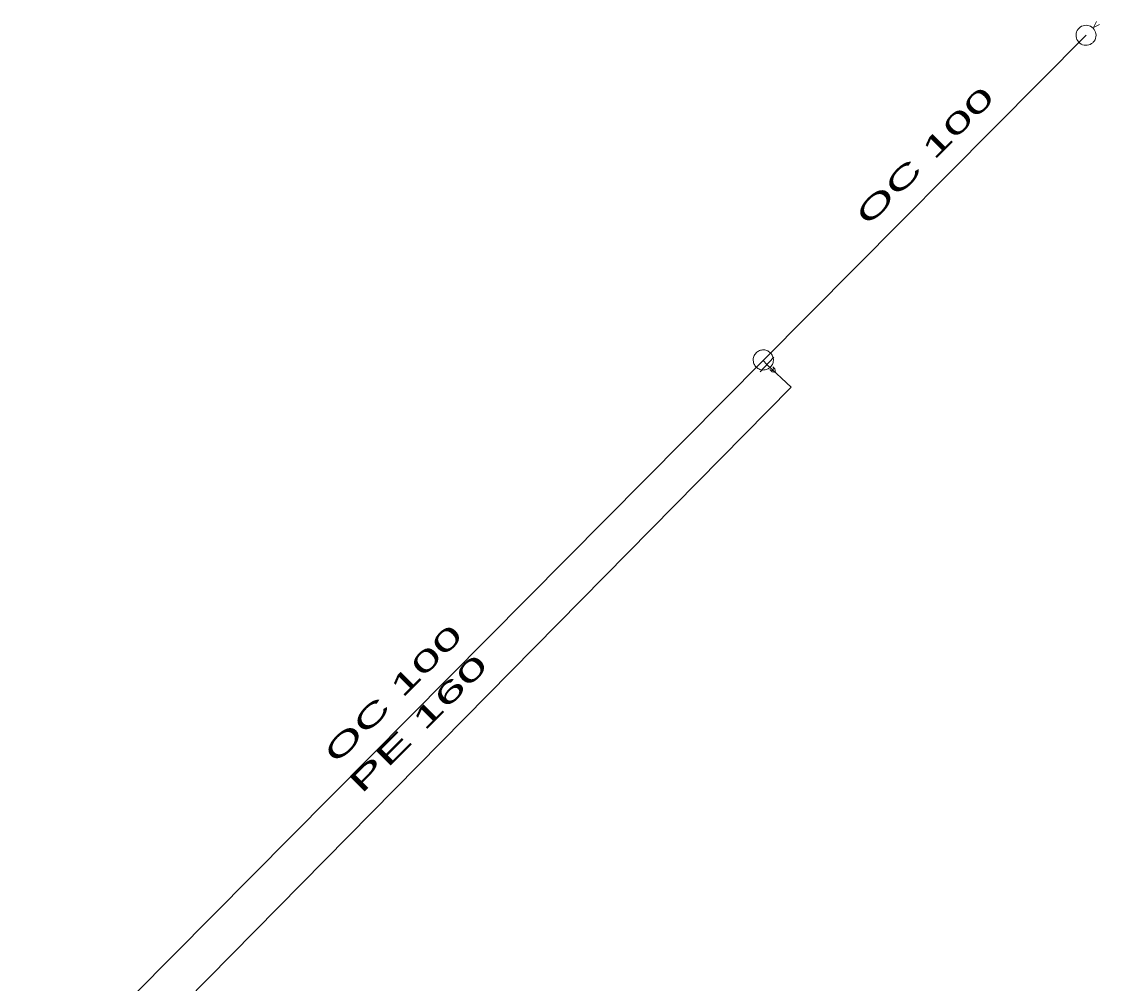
# Model space of a CAD drawing. Extents: x -807203 to -805207, y -993656 to -992505.
# Drawn here: x -806398.8 to -806345.3, y -992839.2 to -992791.5 of the extents above; entities that cross this region are included whole.
import ezdxf

# ---------------------------------------------------------------- set-up
doc = ezdxf.new("R2010")
doc.units = 0
doc.header["$LTSCALE"] = 0.4
for name, color, linetype, lineweight in [('1', 7, 'Continuous', 13), ('14', 7, 'Continuous', 25), ('17', 7, 'Continuous', 25), ('23', 7, 'Continuous', 13), ('34', 7, 'Continuous', 13)]:
    doc.layers.add(name, color=color, linetype=linetype, lineweight=lineweight)

msp = doc.modelspace()

# ---------------------------------------------------------------- linework, layer by layer
at = {"layer": '14', "lineweight": 13}
msp.add_line((-806361.818, -992808.52), (-806361.995, -992808.32), dxfattribs=at)
at = {"layer": '17'}
msp.add_line((-806345.978, -992792.175), (-806361.995, -992808.32), dxfattribs=at)
for points in [[(-806361.995, -992808.32), (-806393.217, -992839.791), (-806398.804, -992845.506)], [(-806397.651, -992847.204), (-806360.609, -992809.633), (-806361.818, -992808.52)]]:
    msp.add_lwpolyline(points, dxfattribs=at)
at = {"layer": '23'}
msp.add_line((-806361.595, -992808.837), (-806361.457, -992808.697), dxfattribs=at)
msp.add_lwpolyline([(-806345.619, -992792.52), (-806345.57, -992792.46), (-806345.531, -992792.394), (-806345.502, -992792.322), (-806345.485, -992792.246), (-806345.48, -992792.169), (-806345.487, -992792.092), (-806345.505, -992792.018), (-806345.535, -992791.947), (-806345.576, -992791.881), (-806345.626, -992791.822), (-806345.685, -992791.772), (-806345.751, -992791.731), (-806345.822, -992791.701), (-806345.897, -992791.684), (-806345.974, -992791.678), (-806346.051, -992791.683), (-806346.127, -992791.7), (-806346.198, -992791.729), (-806346.265, -992791.767), (-806346.324, -992791.817), (-806346.375, -992791.875), (-806346.417, -992791.94), (-806346.448, -992792.012), (-806346.468, -992792.086), (-806346.475, -992792.163), (-806346.472, -992792.24), (-806346.455, -992792.315), (-806346.428, -992792.387), (-806346.39, -992792.455), (-806346.342, -992792.514), (-806346.284, -992792.567), (-806346.22, -992792.61), (-806346.15, -992792.642), (-806346.076, -992792.663), (-806345.999, -992792.672), (-806345.922, -992792.67), (-806345.846, -992792.655), (-806345.774, -992792.629), (-806345.706, -992792.592), (-806345.644, -992792.545)], close=True, dxfattribs=at)
for points in [[(-806345.313, -992791.638), (-806345.603, -992791.79), (-806345.462, -992791.495)], [(-806361.545, -992808.506), (-806361.525, -992808.46), (-806361.509, -992808.41), (-806361.5, -992808.357), (-806361.495, -992808.305), (-806361.496, -992808.252), (-806361.501, -992808.201), (-806361.513, -992808.15), (-806361.531, -992808.1), (-806361.553, -992808.054), (-806361.58, -992808.008), (-806361.612, -992807.967), (-806361.646, -992807.928), (-806361.685, -992807.894), (-806361.729, -992807.863), (-806361.775, -992807.837), (-806361.822, -992807.817), (-806361.872, -992807.803), (-806361.923, -992807.793), (-806361.976, -992807.787), (-806362.029, -992807.788), (-806362.08, -992807.795), (-806362.131, -992807.806), (-806362.181, -992807.823), (-806362.228, -992807.844), (-806362.273, -992807.873), (-806362.314, -992807.904), (-806362.353, -992807.939), (-806362.387, -992807.978), (-806362.417, -992808.021), (-806362.443, -992808.067), (-806362.463, -992808.115), (-806362.479, -992808.166), (-806362.49, -992808.216), (-806362.493, -992808.269), (-806362.493, -992808.32), (-806362.487, -992808.372), (-806362.475, -992808.424), (-806362.458, -992808.474), (-806362.436, -992808.521)], [(-806362.08, -992807.795), (-806362.131, -992807.806), (-806362.181, -992807.823), (-806362.228, -992807.844), (-806362.273, -992807.873), (-806362.314, -992807.904), (-806362.353, -992807.939), (-806362.387, -992807.978), (-806362.417, -992808.021), (-806362.443, -992808.067), (-806362.463, -992808.115), (-806362.479, -992808.166), (-806362.49, -992808.216), (-806362.493, -992808.269), (-806362.493, -992808.32), (-806362.487, -992808.372), (-806362.475, -992808.424), (-806362.458, -992808.474), (-806362.436, -992808.521), (-806362.408, -992808.565), (-806362.378, -992808.607), (-806362.343, -992808.646), (-806362.303, -992808.681), (-806362.26, -992808.711), (-806362.215, -992808.735), (-806362.166, -992808.756), (-806362.117, -992808.771), (-806362.064, -992808.781), (-806362.013, -992808.786), (-806361.961, -992808.785), (-806361.909, -992808.779), (-806361.858, -992808.768), (-806361.808, -992808.751), (-806361.76, -992808.728), (-806361.715, -992808.702), (-806361.675, -992808.671), (-806361.636, -992808.636), (-806361.601, -992808.595), (-806361.571, -992808.554), (-806361.545, -992808.506)], [(-806362.343, -992808.646), (-806362.303, -992808.681), (-806362.26, -992808.711), (-806362.215, -992808.735), (-806362.166, -992808.756), (-806362.117, -992808.771), (-806362.064, -992808.781), (-806362.013, -992808.786), (-806361.961, -992808.785), (-806361.909, -992808.779), (-806361.858, -992808.768), (-806361.808, -992808.751), (-806361.76, -992808.728), (-806361.715, -992808.702), (-806361.675, -992808.671), (-806361.636, -992808.636), (-806361.601, -992808.595), (-806361.571, -992808.554), (-806361.545, -992808.506), (-806361.525, -992808.46), (-806361.509, -992808.41), (-806361.5, -992808.357), (-806361.495, -992808.305), (-806361.496, -992808.252), (-806361.501, -992808.201), (-806361.513, -992808.15), (-806361.531, -992808.1), (-806361.553, -992808.054), (-806361.58, -992808.008), (-806361.612, -992807.967), (-806361.646, -992807.928), (-806361.685, -992807.894), (-806361.729, -992807.863), (-806361.775, -992807.837), (-806361.822, -992807.817), (-806361.872, -992807.803), (-806361.923, -992807.793), (-806361.976, -992807.787), (-806362.029, -992807.788), (-806362.08, -992807.795)], [(-806362.436, -992808.521), (-806362.408, -992808.565), (-806362.378, -992808.607), (-806362.343, -992808.646)], [(-806361.526, -992808.629), (-806361.42, -992808.734), (-806361.383, -992808.911), (-806361.558, -992808.873), (-806361.664, -992808.768)]]:
    msp.add_lwpolyline(points, dxfattribs=at)
at = {"layer": '34'}
msp.add_line((-806362.158, -992808.885), (-806361.476, -992808.154), dxfattribs=at)

# ---------------------------------------------------------------- texts
at = {"layer": '1'}
for s, width, p in [('OC 100', 1.95, (-806356.798, -992801.682)), ('OC 100', 1.95, (-806383.185, -992828.376)), ('PE 160', 2.05, (-806381.937, -992829.863))]:
    msp.add_text(s, height=1, rotation=45, dxfattribs=dict(at, width=width)).set_placement(p)

doc.saveas('drawing.dxf')
